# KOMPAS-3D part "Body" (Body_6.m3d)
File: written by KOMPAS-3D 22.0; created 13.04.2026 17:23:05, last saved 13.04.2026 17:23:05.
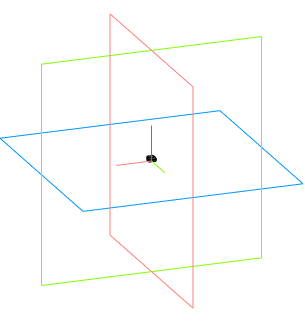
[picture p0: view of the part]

Document properties: Автор: Andrey; Полное имя файла: C:\Users\User1\Documents\Body_6.m3d

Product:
- Part/product: Body

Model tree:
1. Операция без истории:1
